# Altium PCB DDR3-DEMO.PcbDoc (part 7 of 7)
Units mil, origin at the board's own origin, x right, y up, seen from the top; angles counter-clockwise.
Board outline 2827 x 2165.35 mil, 8 copper layers (TOP, GND02, ART03, ART04, PWR05, ART06, GND07, BOTTOM); 111 components, 133 nets, 5542 pads, 873 vias.
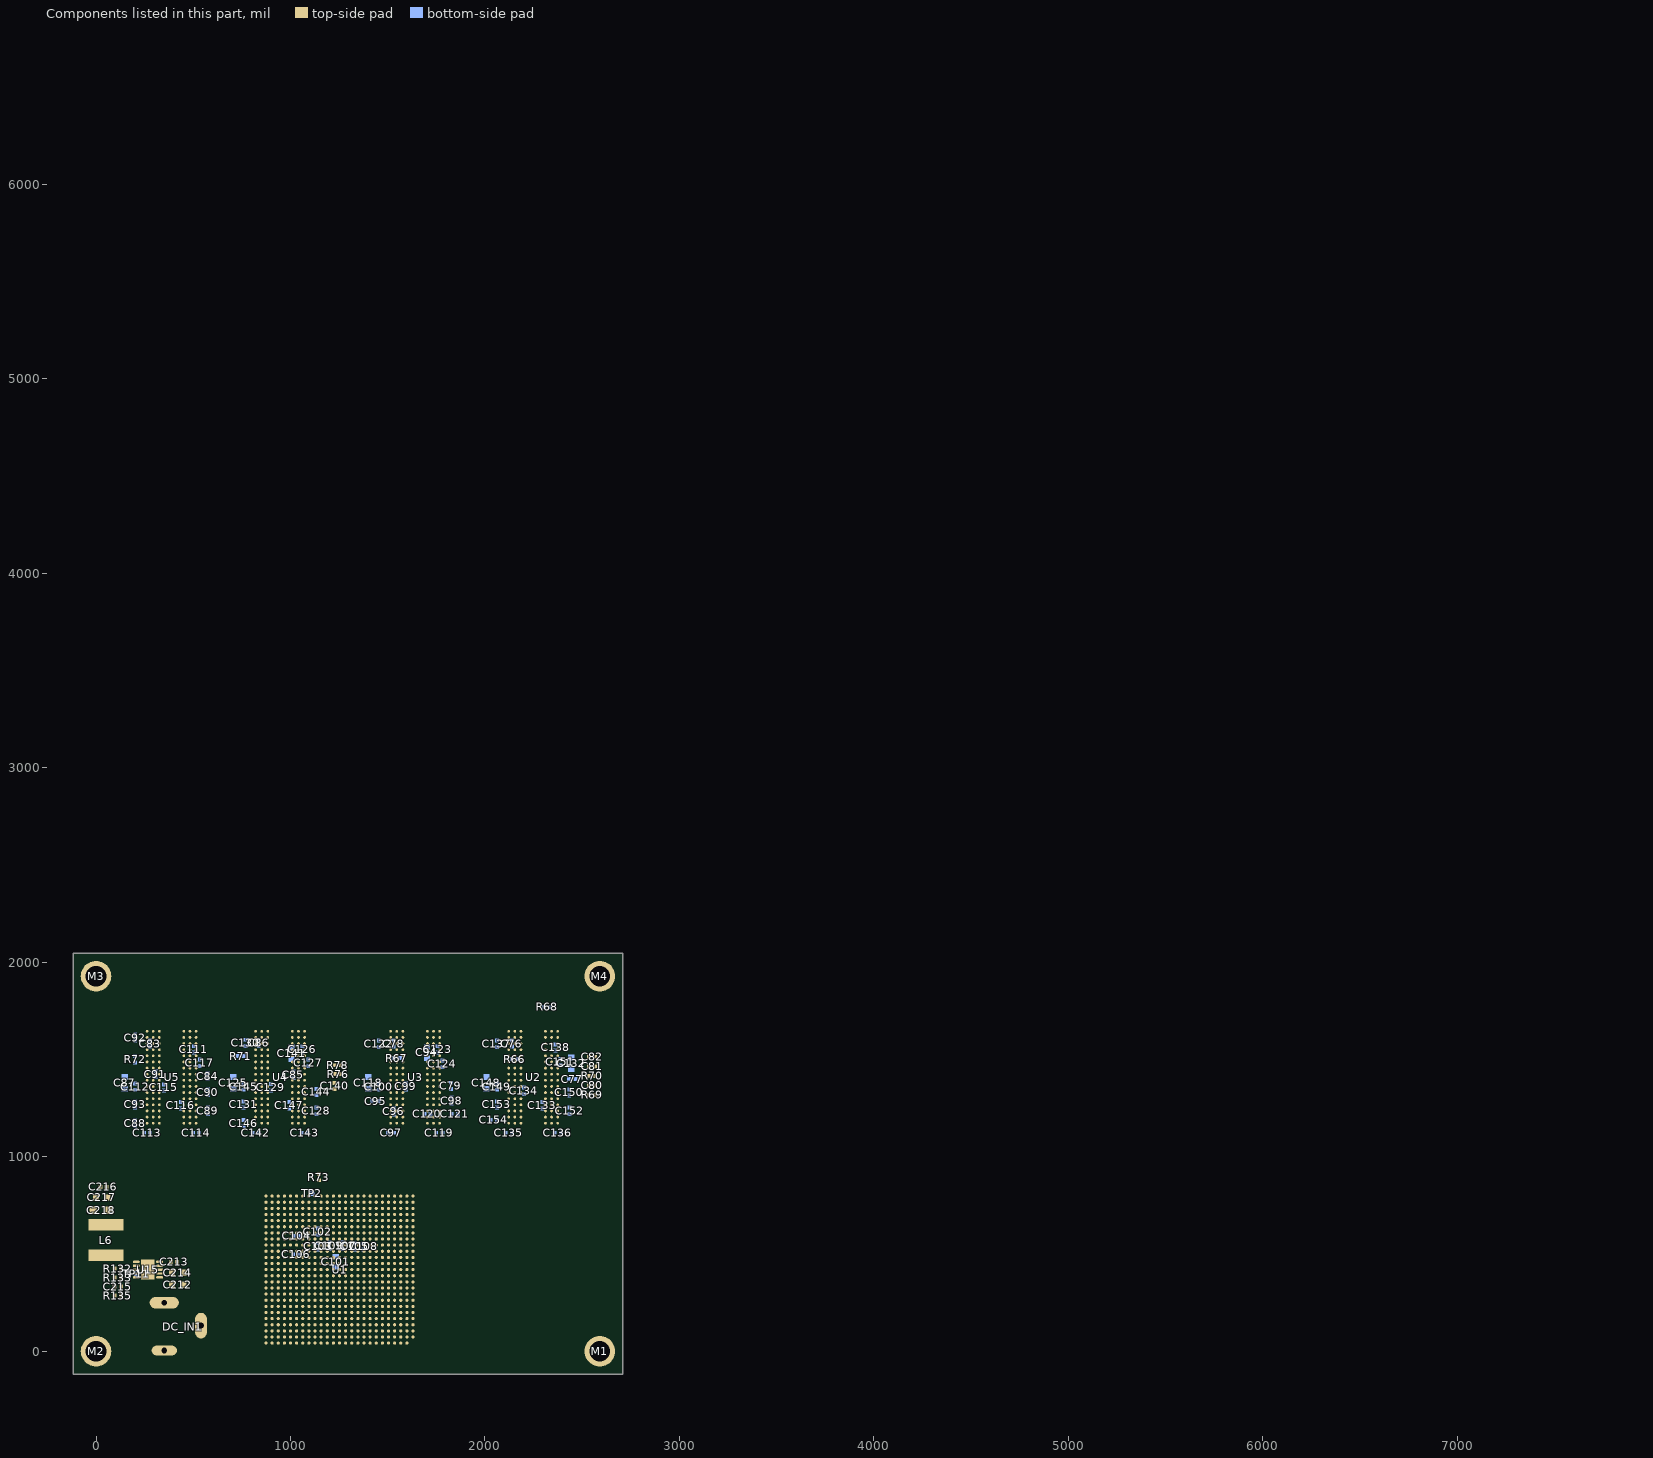
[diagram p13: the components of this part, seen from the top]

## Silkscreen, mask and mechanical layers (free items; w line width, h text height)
Drill Drawing:
  drawing of 2159 lines, arcs and shapes, not listed
  text "Purchase   Order &  Specification   Sheet" at 4496.07,6718.33 h77.51
  text "1.0" at 6028.53,6599.43 h38.75
  text "8" at 7287.5,6597.96 h38.75
  text "Dielectric Material:" at 3607.26,6592.57 h38.75
  text "FR4" at 4614.32,6589.19 h38.75
  text "Board Thickness(MM):" at 5105.79,6589.15 h38.75
  text "Layers:" at 6486.1,6589.15 h38.75
  text "Osp" at 7402.25,6388.76 h38.75
  text "Surface Finished:" at 3608.81,6385.89 h38.75
  text "Gold Finger" at 6676.67,6386.2 h38.75
  text "Flash Gold" at 5280.41,6384.77 h38.75
  text "Hasl" at 4599.67,6383.81 h38.75
  text "Immersion Gold" at 5901.05,6382.86 h38.75
  text "Hasl Lead Free" at 4598.07,6244.72 h38.75
  text "Immersion Tin" at 5277.26,6237.91 h38.75
  text "Immersion Silver" at 5901.5,6237.3 h38.75
  text "Other" at 6680.76,6236 h38.75
  text "Angle" at 4967.72,6095.1 h38.75
  text "No" at 7402.37,6092.74 h38.75
  text "Yes" at 4609.84,6092.15 h38.75
  text "30" at 5945.68,6091.95 h38.75
  text "45" at 6707.09,6091.95 h38.75
  text "20" at 5307.49,6090.77 h38.75
  text "Finger Chamfer:" at 3611.24,6084.22 h38.75
  text "Matte Green" at 5891.71,5944.55 h38.75
  text "Blue" at 5314.45,5939.94 h38.75
  text "Other" at 6697.13,5937.58 h38.75
  text "Green" at 4610.3,5934.99 h38.75
  text "Soldermask Colours:" at 3607.57,5931.89 h38.75
  text "Black" at 5929.81,5792.7 h38.75
  text "Other" at 6701.07,5791.51 h38.75
  text "Silk Screen Colours:" at 3606.06,5787.91 h38.75
  text "White" at 4610.3,5786.17 h38.75
  text "Yellow" at 5311.3,5784.82 h38.75
  text "Spell Mode:" at 3600.26,5604.79 h38.75
  text "Open Windows:" at 5785.71,5602.54 h38.75
  text "None" at 6326.26,5600.96 h38.75
  text "V-cut" at 6310.12,5445.45 h38.75
  text "Stamp Hole" at 7281.77,5443.48 h38.75
  text "Bridge" at 5281.58,5438.52 h38.75
  text "Outline Profile:" at 3603.81,5438.25 h38.75
  text "Router" at 4630.59,5434.03 h38.75
  text "Gjb362A-96" at 6308.94,5297.81 h38.75
  text "Other" at 7284.53,5297.03 h38.75
  text "IPCII" at 4638.07,5295.45 h38.75
  text "IPCIII" at 5279.1,5294.78 h38.75
  text "Inspectionstandard:" at 3600.37,5292.53 h38.75
  text "Yes" at 4638.07,5144.27 h38.75
  text "No" at 5284.34,5143.64 h38.75
  text "Compare With IPC File" at 3600.77,5136.37 h38.75
  text "All via (<=0.5mm) must be filled(except open soldermask via)" at 4601.45,4837.52 h38.75
  text "By gerber" at 7274.69,4836.39 h38.75
  text "Via  Technic:" at 3608.76,4826.78 h38.75
  text "(unit:mil)MIN.track :                    MIN.spacing :                 MIN.hole:" at 3604.03,4679.93 h38.75
  text "5mil" at 5627.04,4677.69 h38.75
  text "16mil\32mil" at 6613.04,4676.69 h38.75
  text "5mil" at 4350.14,4676.19 h38.75
  text "Pressfit holes: The tolerance of                 is+/-0.05mm" at 5093.33,4534.03 h38.75
  text "*" at 6441.04,4531.72 h38.75
  text "Bow and Twist Tolerance:<=0.75%" at 3600.83,4530.94 h38.75
  text "1.  STACKING (dielectric thickness can be adjusted beween +/-2mil,but don,t less than 3.5mil; if inspection is Gjb362A" at 3698.03,4282.5 h32.81
  text "than don,t less than 4mil.)" at 3698.03,4182.5 h32.81
  text "2.  Control Impedance (track width can be adjusted +/-0.5mil , but don,t less than 4mil.)" at 3698.03,4082.5 h32.81
  text "TOP" at 7267.24,3558.97 h39.27
  text "Hoz+Plating" at 6733.3,3557.18 h38.75
  text "3.84" at 3883.87,3448.34 h39.27
  text "mil" at 4061.34,3448.12 h38.75
  text "pp(3313)" at 4781.75,3448.12 h39.27
  text "1oz" at 6766.44,3340.81 h39.27
  text "GND02" at 7267.24,3339.28 h39.27
  text "5.12" at 3890.42,3228.65 h39.27
  text "mil" at 4061.34,3228.44 h38.75
  text "Core" at 4781.75,3228.44 h39.27
  text "1oz" at 6766.44,3121.13 h39.27
  text "ART03" at 7267.24,3119.6 h39.27
  text "4.09" at 3870.78,3008.97 h39.27
  text "mil" at 4061.34,3008.75 h38.75
  text "pp(1080+106)" at 4781.75,3008.75 h39.27
  text "1oz" at 6766.44,2901.44 h39.27
  text "ART04" at 7267.24,2899.91 h39.27
  text "5.12" at 3890.42,2789.28 h39.27
  text "mil" at 4061.34,2789.07 h38.75
  text "Core" at 4781.75,2789.07 h39.27
  text "1oz" at 6766.44,2681.76 h39.27
  text "PWR05" at 7267.24,2680.22 h39.27
  text "4.09" at 3870.78,2569.6 h39.27
  text "pp(1080+106)" at 4781.75,2569.75 h39.27
  text "mil" at 4061.34,2569.38 h38.75
  text "1oz" at 6766.44,2462.07 h39.27
  text "ART06" at 7267.24,2460.54 h39.27
  text "5.12" at 3890.42,2349.91 h39.27
  text "mil" at 4061.34,2349.7 h38.75
  text "Core" at 4781.75,2349.7 h39.27
  text "1oz" at 6766.44,2242.39 h39.27
  text "GND07" at 7267.24,2240.85 h39.27
  text "pp(3313)" at 4781.75,2135.12 h39.27
  text "3.84" at 3883.87,2130.23 h39.27
  text "mil" at 4061.34,2130.01 h38.75
  text "BOTTOM" at 7267.24,2021.17 h39.27
  text "Hoz+Plating" at 6738.59,2007.53 h38.75
  text "ref layer" at 6561.06,1432.95 h32.81
  text "+/-10%" at 5879.94,1315.74 h38.75
  text "L1/L8" at 3972.49,1309.82 h39.27
  text "6" at 4627.85,1309.47 h39.27
  text "L2/7" at 6532.27,1308.68 h39.27
  text "50" at 5272.76,1306.32 h39.27
  text "+/-10%" at 5879.94,1205.89 h38.75
  text "L3/L4" at 3972.49,1199.98 h39.27
  text "6" at 4627.85,1199.62 h39.27
  text "L2/5" at 6532.27,1198.84 h39.27
  text "50" at 5272.76,1196.47 h39.27
  text "+/-10%" at 5879.94,1096.05 h38.75
  text "L6" at 3972.49,1090.14 h39.27
  text "4.1" at 4627.85,1089.78 h39.27
  text "L5/7" at 6532.27,1088.99 h39.27
  text "50" at 5272.76,1086.63 h39.27
  text "ref layer" at 6582.64,560.85 h32.81
  text "L2/7" at 6540.27,441.68 h39.27
  text "4.5/9" at 4620.47,437.29 h39.27
  text "+/-10%" at 5915.53,436.59 h38.75
  text "100" at 5240.51,434.14 h39.27
  text "L1/L8" at 4004.92,427.84 h39.27
  text "L2/5" at 6540.27,331.84 h39.27
  text "L3/L4" at 4008.49,330.98 h39.27
  text "4.5/6" at 4620.47,327.45 h39.27
  text "+/-10%" at 5915.53,326.75 h38.75
  text "100" at 5240.51,324.3 h39.27
  text "L5/7" at 6541.27,223.99 h39.27
  text "5.0/7.0" at 4620.47,217.61 h39.27
  text "+/-10%" at 5915.53,216.9 h38.75
  text "100" at 5240.51,214.46 h39.27
  text "L6" at 4004.92,208.15 h39.27
  text "Note:If etch layer don't have  above impedance track pls ignore" at 3909.25,-164.4 h51.67
  text ".Legend" at -441.58,-1289.65 h30

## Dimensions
-118.11,-118.11 to -118.11,2047.24 on Mechanical 1
-118.11,-118.11 to 2708.89,-118.11 on Mechanical 1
